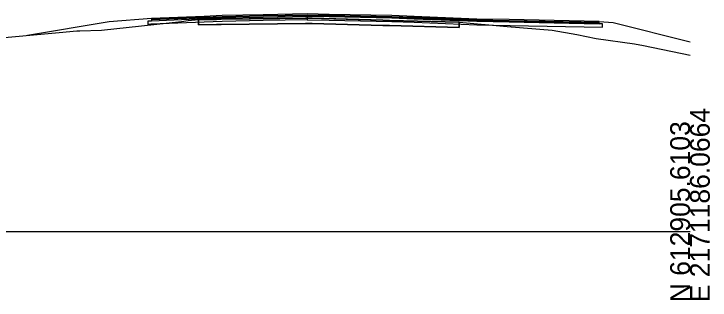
# Model space of a CAD drawing. Extents: x -26 to 1303, y -3010 to 12038.
# Drawn here: x 204.4 to 302.8, y 5990.3 to 6030.8 of the extents above; entities that cross this region are included whole.
import ezdxf

# ---------------------------------------------------------------- set-up
doc = ezdxf.new("R2010")
doc.units = 0
for name, color, linetype in [('RD_GPK_XS_Cell', 7, 'Continuous'), ('RD_XS_Base', 7, 'Continuous'), ('RD_XS_ExGround', 7, 'Continuous'), ('RD_XS_ExPaveRet', 7, 'Continuous'), ('RD_XS_Greenside', 7, 'Continuous'), ('RD_XS_Pave', 7, 'Continuous'), ('RD_XS_PaveOvlay_CP', 7, 'Continuous'), ('RD_XS_TieSlope', 7, 'Continuous')]:
    doc.layers.add(name, color=color, linetype=linetype)

msp = doc.modelspace()

# ---------------------------------------------------------------- linework, layer by layer
at = {"layer": 'RD_GPK_XS_Cell'}
msp.add_line((150, 6000), (300, 6000), dxfattribs=at)
at = {"layer": 'RD_XS_Base'}
for p, q in [((239.618, 6030.341), (245.828, 6030.466)), ((245.828, 6030.583), (245.828, 6030.625)), ((245.828, 6030.625), (245.828, 6030.453)), ((245.828, 6030.466), (245.828, 6030.583)), ((245.828, 6030.466), (245.828, 6030.466)), ((248.955, 6030.403), (245.828, 6030.466)), ((245.828, 6030.466), (245.828, 6030.466)), ((245.828, 6030.466), (245.828, 6030.336)), ((245.828, 6030.453), (245.828, 6029.966)), ((257.828, 6030.226), (248.955, 6030.403)), ((223.328, 6029.806), (223.701, 6029.82)), ((223.328, 6029.679), (223.328, 6029.806)), ((223.328, 6029.306), (223.328, 6029.679)), ((223.701, 6029.82), (223.828, 6029.826)), ((223.828, 6029.826), (231.285, 6030.124)), ((231.285, 6029.624), (223.828, 6029.326)), ((231.285, 6030.124), (233.828, 6030.225)), ((233.828, 6029.725), (231.285, 6029.624)), ((233.828, 6030.225), (239.618, 6030.341)), ((239.618, 6029.841), (233.828, 6029.725)), ((245.828, 6029.966), (239.618, 6029.841)), ((245.828, 6030.336), (245.828, 6029.966)), ((245.828, 6029.966), (248.955, 6029.903)), ((248.955, 6029.903), (257.828, 6029.726)), ((260.986, 6030.099), (257.828, 6030.226)), ((257.828, 6029.726), (260.986, 6029.599)), ((269.828, 6029.746), (260.986, 6030.099)), ((260.986, 6029.599), (269.828, 6029.246)), ((274.431, 6029.654), (269.828, 6029.746)), ((287.128, 6029.4), (274.431, 6029.654)), ((223.701, 6029.32), (223.328, 6029.306)), ((223.828, 6029.326), (223.701, 6029.32)), ((269.828, 6029.246), (274.564, 6029.151)), ((274.564, 6029.151), (287.628, 6028.89)), ((287.262, 6029.397), (287.128, 6029.4)), ((287.628, 6029.39), (287.262, 6029.397)), ((287.628, 6029.255), (287.628, 6029.39)), ((287.628, 6028.89), (287.628, 6029.255))]:
    msp.add_line(p, q, dxfattribs=at)
at = {"layer": 'RD_XS_ExGround'}
msp.add_lwpolyline([(200.9, 6027.237), (210.772, 6028.157), (213.238, 6028.373), (213.691, 6028.372), (216.732, 6028.495), (228.059, 6029.725), (228.992, 6029.832), (230.446, 6029.983), (233.684, 6030.027), (246.113, 6030.181), (256.532, 6029.902), (267.34, 6029.617), (274.128, 6029.026), (280.485, 6028.499), (284.003, 6027.894), (286.74, 6027.306), (292.124, 6026.546), (293.44, 6026.32), (300, 6024.96)], dxfattribs=at)
at = {"layer": 'RD_XS_ExPaveRet'}
for points in [[(267.34, 6029.617), (267.34, 6029.576), (267.34, 6028.867), (257.488, 6029.127), (256.532, 6029.152), (246.54, 6029.42), (246.113, 6029.431), (245.595, 6029.425), (233.684, 6029.277), (233.001, 6029.268), (230.446, 6029.233), (230.446, 6029.296), (230.446, 6029.983), (233.001, 6030.018), (233.684, 6030.027), (245.595, 6030.175), (246.113, 6030.181), (246.54, 6030.17), (256.532, 6029.902), (257.488, 6029.877), (267.34, 6029.617)], [(257.488, 6029.877), (256.532, 6029.902), (246.54, 6030.17), (246.113, 6030.181), (245.595, 6030.175), (233.684, 6030.027), (233.001, 6030.018), (230.446, 6029.983), (230.446, 6029.296), (230.446, 6029.233), (233.001, 6029.268), (233.684, 6029.277), (245.595, 6029.425), (246.113, 6029.431), (246.54, 6029.42), (256.532, 6029.152), (257.488, 6029.127), (267.34, 6028.867), (267.34, 6029.576), (267.34, 6029.617), (257.488, 6029.877)]]:
    msp.add_lwpolyline(points, dxfattribs=at)
at = {"layer": 'RD_XS_Greenside'}
for p, q in [((217.828, 6029.664), (206.272, 6027.738)), ((289.128, 6029.558), (300, 6026.84))]:
    msp.add_line(p, q, dxfattribs=at)
at = {"layer": 'RD_XS_Pave'}
for p, q in [((231.285, 6030.442), (223.828, 6030.144)), ((233.828, 6030.544), (231.285, 6030.442)), ((239.618, 6030.659), (233.828, 6030.544)), ((239.618, 6030.5), (233.828, 6030.384)), ((233.828, 6030.385), (239.618, 6030.5)), ((245.828, 6030.784), (239.618, 6030.659)), ((245.828, 6030.625), (239.618, 6030.5)), ((239.618, 6030.5), (245.828, 6030.625)), ((239.618, 6030.341), (245.828, 6030.466)), ((248.955, 6030.721), (245.828, 6030.784)), ((245.828, 6030.583), (245.828, 6030.625)), ((245.828, 6030.625), (248.955, 6030.562)), ((248.955, 6030.562), (245.828, 6030.625)), ((245.828, 6030.625), (245.828, 6030.625)), ((245.828, 6030.625), (245.828, 6030.625)), ((245.828, 6030.625), (245.828, 6030.583)), ((245.828, 6030.466), (245.828, 6030.583)), ((245.828, 6030.583), (245.828, 6030.466)), ((245.828, 6030.466), (245.828, 6030.466)), ((245.828, 6030.466), (245.828, 6030.466)), ((245.828, 6030.466), (248.955, 6030.403)), ((257.828, 6030.544), (248.955, 6030.721)), ((248.955, 6030.562), (257.828, 6030.385)), ((257.828, 6030.385), (248.955, 6030.562)), ((248.955, 6030.403), (257.828, 6030.226)), ((260.986, 6030.417), (257.828, 6030.544)), ((269.828, 6030.064), (260.986, 6030.417)), ((231.285, 6030.283), (223.828, 6029.985)), ((223.828, 6029.985), (231.285, 6030.283)), ((223.828, 6030.144), (223.828, 6030.103)), ((223.828, 6029.826), (231.285, 6030.124)), ((223.828, 6030.103), (223.828, 6029.985)), ((223.828, 6029.985), (223.828, 6029.944)), ((223.828, 6029.944), (223.828, 6029.826)), ((233.828, 6030.384), (231.285, 6030.283)), ((231.285, 6030.283), (233.828, 6030.384)), ((231.285, 6030.124), (233.828, 6030.225)), ((233.828, 6030.225), (239.618, 6030.341)), ((257.828, 6030.385), (260.986, 6030.258)), ((260.986, 6030.258), (257.828, 6030.385)), ((257.828, 6030.226), (260.986, 6030.099)), ((260.986, 6030.258), (269.828, 6029.905)), ((269.828, 6029.905), (260.986, 6030.258)), ((260.986, 6030.099), (269.828, 6029.746)), ((274.431, 6029.972), (269.828, 6030.064)), ((269.828, 6029.905), (274.431, 6029.813)), ((274.431, 6029.813), (269.828, 6029.905)), ((269.828, 6029.746), (274.431, 6029.654)), ((287.128, 6029.718), (274.431, 6029.972)), ((274.431, 6029.813), (287.128, 6029.559)), ((287.128, 6029.559), (274.431, 6029.813)), ((274.431, 6029.654), (287.128, 6029.4)), ((287.128, 6029.675), (287.128, 6029.718)), ((287.128, 6029.559), (287.128, 6029.675)), ((287.128, 6029.516), (287.128, 6029.559)), ((287.128, 6029.4), (287.128, 6029.516))]:
    msp.add_line(p, q, dxfattribs=at)
at = {"layer": 'RD_XS_PaveOvlay_CP'}
for p, q in [((231.285, 6030.442), (223.828, 6030.144)), ((233.828, 6030.544), (231.285, 6030.442)), ((239.618, 6030.659), (233.828, 6030.544)), ((245.828, 6030.784), (239.618, 6030.659)), ((248.955, 6030.721), (245.828, 6030.784)), ((257.828, 6030.544), (248.955, 6030.721)), ((260.986, 6030.417), (257.828, 6030.544)), ((269.828, 6030.064), (260.986, 6030.417)), ((274.431, 6029.972), (269.828, 6030.064)), ((287.128, 6029.718), (274.431, 6029.972))]:
    msp.add_line(p, q, dxfattribs=at)
at = {"layer": 'RD_XS_TieSlope'}
for p, q in [((223.828, 6030.144), (217.828, 6029.664)), ((287.128, 6029.718), (289.128, 6029.558))]:
    msp.add_line(p, q, dxfattribs=at)

# ---------------------------------------------------------------- texts
at = {"layer": 'RD_GPK_XS_Cell'}
for s, p in [('E 2171186.0664', (302.8, 5990)), ('N 612905.6103', (300, 5990))]:
    msp.add_text(s, height=2.8, rotation=90, dxfattribs=at).set_placement(p)

doc.saveas('drawing.dxf')
